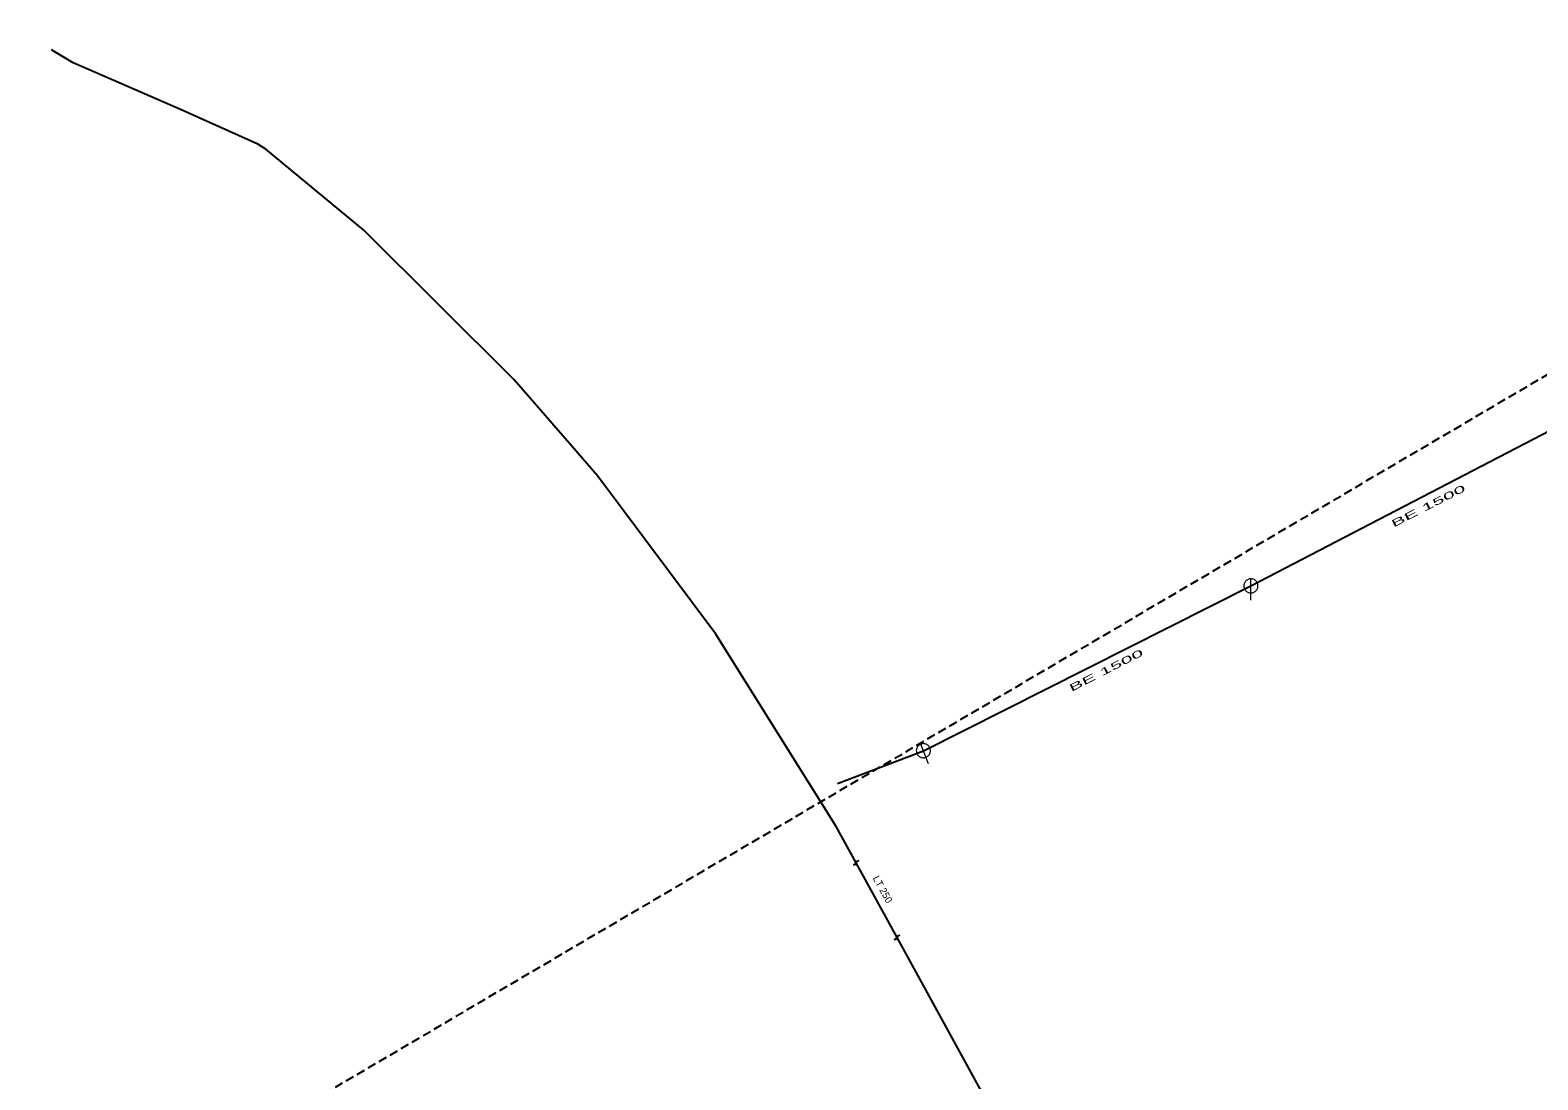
# Model space of a CAD drawing. Extents: x -807203 to -805207, y -993656 to -992505.
# Drawn here: x -806957.5 to -806744.2, y -992783.3 to -992634.9 of the extents above; entities that cross this region are included whole.
import ezdxf

# ---------------------------------------------------------------- set-up
doc = ezdxf.new("R2010")
doc.units = 0
doc.header["$LTSCALE"] = 0.4
doc.linetypes.add('MEDIUM_DASHED', pattern=[4.5, 3, -1.5])
for name, color, linetype, lineweight in [('1', 7, 'Continuous', 13), ('14', 7, 'Continuous', 25), ('17', 7, 'Continuous', 25), ('22', 7, 'Continuous', 13), ('47', 7, 'Continuous', 13), ('63', 7, 'MEDIUM_DASHED', 25)]:
    doc.layers.add(name, color=color, linetype=linetype, lineweight=lineweight)

msp = doc.modelspace()

# ---------------------------------------------------------------- linework, layer by layer
at = {"layer": '14'}
for points in [[(-806784.8, -992713.495), (-806740.059, -992690.25), (-806698.98, -992669.26), (-806697.199, -992666.514), (-806693.41, -992660.67)], [(-806843.28, -992741.42), (-806831.14, -992736.8), (-806784.8, -992713.495)]]:
    msp.add_lwpolyline(points, dxfattribs=at)
at = {"layer": '17'}
msp.add_line((-806834.87, -992763.203), (-806840.657, -992752.666), dxfattribs=at)
for points in [[(-806840.657, -992752.666), (-806843.489, -992747.51), (-806859.199, -992722.423), (-806860.51, -992720.329), (-806877.239, -992697.94), (-806880.892, -992693.736), (-806889.02, -992684.34), (-806910.3, -992663.199), (-806924.18, -992651.73), (-806925.32, -992651.05), (-806936.25, -992646.12), (-806951.449, -992639.539), (-806954.519, -992637.699)], [(-806744.869, -992895.849), (-806751.715, -992883.767), (-806753.16, -992884.579), (-806762.344, -992889.559), (-806763.23, -992888.129), (-806769.25, -992877.71), (-806781.199, -992856.899), (-806796.3, -992830.96), (-806805.559, -992815.579), (-806823.289, -992784.289), (-806834.87, -992763.203)]]:
    msp.add_lwpolyline(points, dxfattribs=at)
at = {"layer": '22'}
for p, q in [((-806784.8, -992715.495), (-806784.799, -992712.495)), ((-806830.428, -992738.669), (-806831.495, -992735.865))]:
    msp.add_line(p, q, dxfattribs=at)
for points in [[(-806783.8, -992713.495), (-806783.805, -992713.386), (-806783.823, -992713.278), (-806783.853, -992713.172), (-806783.893, -992713.071), (-806783.945, -992712.974), (-806784.007, -992712.884), (-806784.079, -992712.801), (-806784.159, -992712.727), (-806784.247, -992712.661), (-806784.341, -992712.606), (-806784.441, -992712.561), (-806784.546, -992712.528), (-806784.653, -992712.506), (-806784.762, -992712.496), (-806784.872, -992712.498), (-806784.98, -992712.512), (-806785.087, -992712.537), (-806785.19, -992712.574), (-806785.288, -992712.623), (-806785.38, -992712.681), (-806785.466, -992712.75), (-806785.543, -992712.827), (-806785.612, -992712.913), (-806785.671, -992713.005), (-806785.719, -992713.103), (-806785.756, -992713.206), (-806785.782, -992713.313), (-806785.796, -992713.421), (-806785.799, -992713.531), (-806785.789, -992713.64), (-806785.768, -992713.747), (-806785.734, -992713.851), (-806785.69, -992713.951), (-806785.635, -992714.046), (-806785.569, -992714.134), (-806785.495, -992714.214), (-806785.412, -992714.286), (-806785.322, -992714.348), (-806785.226, -992714.4), (-806785.124, -992714.441), (-806785.019, -992714.471), (-806784.911, -992714.489), (-806784.801, -992714.495), (-806784.692, -992714.489), (-806784.584, -992714.471), (-806784.479, -992714.442), (-806784.377, -992714.401), (-806784.28, -992714.349), (-806784.19, -992714.287), (-806784.107, -992714.216), (-806784.032, -992714.136), (-806783.967, -992714.048), (-806783.911, -992713.954), (-806783.867, -992713.854), (-806783.833, -992713.75), (-806783.811, -992713.642), (-806783.801, -992713.533)], [(-806830.205, -992736.444), (-806830.249, -992736.345), (-806830.304, -992736.25), (-806830.37, -992736.162), (-806830.443, -992736.081), (-806830.526, -992736.009), (-806830.616, -992735.947), (-806830.713, -992735.895), (-806830.814, -992735.855), (-806830.92, -992735.824), (-806831.027, -992735.806), (-806831.137, -992735.8), (-806831.247, -992735.806), (-806831.355, -992735.824), (-806831.46, -992735.853), (-806831.562, -992735.894), (-806831.658, -992735.946), (-806831.749, -992736.007), (-806831.832, -992736.078), (-806831.906, -992736.159), (-806831.972, -992736.246), (-806832.028, -992736.341), (-806832.072, -992736.44), (-806832.106, -992736.545), (-806832.129, -992736.652), (-806832.139, -992736.761), (-806832.137, -992736.87), (-806832.123, -992736.979), (-806832.097, -992737.085), (-806832.06, -992737.189), (-806832.012, -992737.287), (-806831.954, -992737.38), (-806831.886, -992737.465), (-806831.809, -992737.543), (-806831.724, -992737.612), (-806831.631, -992737.671), (-806831.533, -992737.719), (-806831.43, -992737.757), (-806831.324, -992737.783), (-806831.216, -992737.797), (-806831.106, -992737.799), (-806830.997, -992737.79), (-806830.89, -992737.768), (-806830.785, -992737.735), (-806830.685, -992737.691), (-806830.59, -992737.635), (-806830.502, -992737.571), (-806830.422, -992737.496), (-806830.35, -992737.413), (-806830.288, -992737.323), (-806830.235, -992737.227), (-806830.194, -992737.126), (-806830.164, -992737.021), (-806830.145, -992736.913), (-806830.14, -992736.804), (-806830.145, -992736.694), (-806830.163, -992736.586), (-806830.192, -992736.48)]]:
    msp.add_lwpolyline(points, close=True, dxfattribs=at)
at = {"layer": '47'}
for p, q in [((-806840.265, -992752.339), (-806840.753, -992752.489)), ((-806834.478, -992762.876), (-806834.966, -992763.026))]:
    msp.add_line(p, q, dxfattribs=at)
for points in [[(-806840.265, -992752.339), (-806841.048, -992752.992), (-806840.56, -992752.842)], [(-806834.478, -992762.876), (-806835.261, -992763.529), (-806834.773, -992763.379)]]:
    msp.add_lwpolyline(points, dxfattribs=at)
at = {"layer": '63'}
msp.add_lwpolyline([(-807189.02, -992945.815), (-806576.348, -992585.749), (-806576.348, -992585.749), (-805244.939, -992598.309), (-805244.939, -992598.309), (-805207.257, -992947.211), (-805207.257, -992947.211), (-805210.049, -993545.926), (-805210.049, -993545.926), (-805797.599, -993596.168), (-805797.599, -993596.168), (-807062.019, -993558.487), (-807062.019, -993558.487)], close=True, dxfattribs=at)

# ---------------------------------------------------------------- texts
at = {"layer": '1', "width": 2.25}
for p in [(-806764.62, -992705.247), (-806810.204, -992728.493)]:
    msp.add_text('BE 1500 ', height=1, rotation=27, dxfattribs=at).set_placement(p)
at = {"layer": '1'}
msp.add_text('LT 250', height=1, rotation=299, dxfattribs=at).set_placement((-806838.344, -992754.83))

doc.saveas('drawing.dxf')
